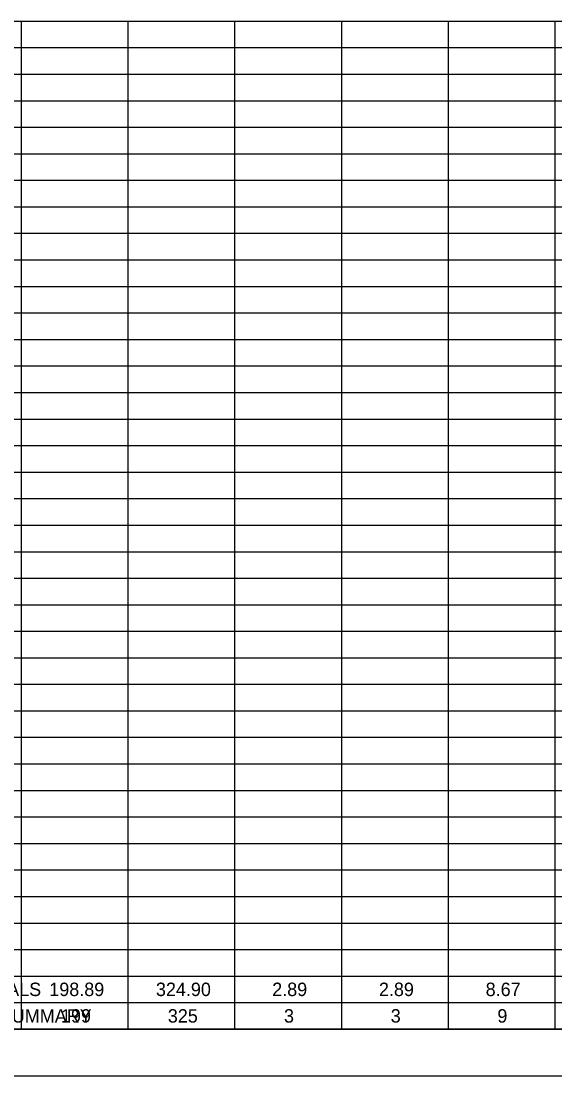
# Model space of a CAD drawing. Extents: x 0 to 34, y 0 to 22.
# Drawn here: x 10.32 to 16.02, y 0 to 11.28 of the extents above; entities that cross this region are included whole.
import ezdxf

# ---------------------------------------------------------------- set-up
doc = ezdxf.new("R2010")
doc.units = 0
for name, color, linetype in [('SH_Border', 7, 'Continuous'), ('SH_Cut_Line', 7, 'Continuous'), ('SH_Text', 7, 'Continuous')]:
    doc.layers.add(name, color=color, linetype=linetype)

msp = doc.modelspace()

# ---------------------------------------------------------------- linework, layer by layer
at = {"layer": 'SH_Border'}
msp.add_lwpolyline([(1.5, 21.5), (33.5, 21.5), (33.5, 0.5), (1.5, 0.5)], close=True, dxfattribs=at)
at = {"layer": 'SH_Cut_Line'}
msp.add_lwpolyline([(0, 0), (34, 0), (34, 22), (0, 22)], close=True, dxfattribs=at)
at = {"layer": 'SH_Text'}
for p, q in [((8.033, 11.284), (10.315, 11.284)), ((10.315, 11.284), (11.457, 11.284)), ((10.315, 11.284), (10.315, 10.149)), ((11.457, 11.284), (13.739, 11.284)), ((11.457, 11.284), (11.457, 10.149)), ((12.598, 11.284), (12.598, 10.149)), ((13.739, 11.284), (14.881, 11.284)), ((13.739, 11.284), (13.739, 10.149)), ((14.881, 11.284), (16.022, 11.284)), ((14.881, 11.284), (14.881, 10.149)), ((16.022, 11.284), (24.011, 11.284)), ((16.022, 11.284), (16.022, 10.149)), ((8.033, 11), (10.315, 11)), ((10.315, 11), (11.457, 11)), ((11.457, 11), (13.739, 11)), ((13.739, 11), (14.881, 11)), ((14.881, 11), (16.022, 11)), ((16.022, 11), (24.011, 11)), ((8.033, 10.716), (10.315, 10.716)), ((10.315, 10.716), (11.457, 10.716)), ((11.457, 10.716), (13.739, 10.716)), ((13.739, 10.716), (14.881, 10.716)), ((14.881, 10.716), (16.022, 10.716)), ((16.022, 10.716), (24.011, 10.716)), ((8.033, 10.432), (10.315, 10.432)), ((10.315, 10.432), (11.457, 10.432)), ((11.457, 10.432), (13.739, 10.432)), ((13.739, 10.432), (14.881, 10.432)), ((14.881, 10.432), (16.022, 10.432)), ((16.022, 10.432), (24.011, 10.432)), ((8.033, 10.149), (10.315, 10.149)), ((10.315, 10.149), (11.457, 10.149)), ((10.315, 10.149), (10.315, 9.581)), ((11.457, 10.149), (13.739, 10.149)), ((11.457, 10.149), (11.457, 9.581)), ((12.598, 10.149), (12.598, 9.581)), ((13.739, 10.149), (14.881, 10.149)), ((13.739, 10.149), (13.739, 9.581)), ((14.881, 10.149), (16.022, 10.149)), ((14.881, 10.149), (14.881, 9.581)), ((16.022, 10.149), (24.011, 10.149)), ((16.022, 10.149), (16.022, 9.581)), ((8.033, 9.865), (10.315, 9.865)), ((10.315, 9.865), (11.457, 9.865)), ((11.457, 9.865), (13.739, 9.865)), ((13.739, 9.865), (14.881, 9.865)), ((14.881, 9.865), (16.022, 9.865)), ((16.022, 9.865), (24.011, 9.865)), ((8.033, 9.581), (10.315, 9.581)), ((10.315, 9.581), (11.457, 9.581)), ((10.315, 9.581), (10.315, 9.297)), ((11.457, 9.581), (13.739, 9.581)), ((11.457, 9.581), (11.457, 9.297)), ((12.598, 9.581), (12.598, 9.297)), ((13.739, 9.581), (14.881, 9.581)), ((13.739, 9.581), (13.739, 9.297)), ((14.881, 9.581), (16.022, 9.581)), ((14.881, 9.581), (14.881, 9.297)), ((16.022, 9.581), (24.011, 9.581)), ((16.022, 9.581), (16.022, 9.297)), ((8.033, 9.297), (10.315, 9.297)), ((10.315, 9.297), (11.457, 9.297)), ((10.315, 9.297), (10.315, 9.014)), ((11.457, 9.297), (13.739, 9.297)), ((11.457, 9.297), (11.457, 9.014)), ((12.598, 9.297), (12.598, 9.014)), ((13.739, 9.297), (14.881, 9.297)), ((13.739, 9.297), (13.739, 9.014)), ((14.881, 9.297), (16.022, 9.297)), ((14.881, 9.297), (14.881, 9.014)), ((16.022, 9.297), (24.011, 9.297)), ((16.022, 9.297), (16.022, 9.014)), ((8.033, 9.014), (10.315, 9.014)), ((10.315, 9.014), (11.457, 9.014)), ((10.315, 9.014), (10.315, 8.73)), ((11.457, 9.014), (13.739, 9.014)), ((11.457, 9.014), (11.457, 8.73)), ((12.598, 9.014), (12.598, 8.73)), ((13.739, 9.014), (14.881, 9.014)), ((13.739, 9.014), (13.739, 8.73)), ((14.881, 9.014), (16.022, 9.014)), ((14.881, 9.014), (14.881, 8.73)), ((16.022, 9.014), (24.011, 9.014)), ((16.022, 9.014), (16.022, 8.73)), ((8.033, 8.73), (10.315, 8.73)), ((10.315, 8.73), (11.457, 8.73)), ((10.315, 8.73), (10.315, 8.446)), ((11.457, 8.73), (13.739, 8.73)), ((11.457, 8.73), (11.457, 8.446)), ((12.598, 8.73), (12.598, 8.446)), ((13.739, 8.73), (14.881, 8.73)), ((13.739, 8.73), (13.739, 8.446)), ((14.881, 8.73), (16.022, 8.73)), ((14.881, 8.73), (14.881, 8.446)), ((16.022, 8.73), (24.011, 8.73)), ((16.022, 8.73), (16.022, 8.446)), ((8.033, 8.446), (10.315, 8.446)), ((10.315, 8.446), (11.457, 8.446)), ((10.315, 8.446), (10.315, 8.162)), ((11.457, 8.446), (13.739, 8.446)), ((11.457, 8.446), (11.457, 8.162)), ((12.598, 8.446), (12.598, 8.162)), ((13.739, 8.446), (14.881, 8.446)), ((13.739, 8.446), (13.739, 8.162)), ((14.881, 8.446), (16.022, 8.446)), ((14.881, 8.446), (14.881, 8.162)), ((16.022, 8.446), (24.011, 8.446)), ((16.022, 8.446), (16.022, 8.162)), ((8.033, 8.162), (10.315, 8.162)), ((10.315, 8.162), (11.457, 8.162)), ((10.315, 8.162), (10.315, 7.878)), ((11.457, 8.162), (13.739, 8.162)), ((11.457, 8.162), (11.457, 7.878)), ((12.598, 8.162), (12.598, 7.878)), ((13.739, 8.162), (14.881, 8.162)), ((13.739, 8.162), (13.739, 7.878)), ((14.881, 8.162), (16.022, 8.162)), ((14.881, 8.162), (14.881, 7.878)), ((16.022, 8.162), (24.011, 8.162)), ((16.022, 8.162), (16.022, 7.878)), ((8.033, 7.878), (10.315, 7.878)), ((10.315, 7.878), (11.457, 7.878)), ((10.315, 7.878), (10.315, 7.595)), ((11.457, 7.878), (13.739, 7.878)), ((11.457, 7.878), (11.457, 7.595)), ((12.598, 7.878), (12.598, 7.595)), ((13.739, 7.878), (14.881, 7.878)), ((13.739, 7.878), (13.739, 7.595)), ((14.881, 7.878), (16.022, 7.878)), ((14.881, 7.878), (14.881, 7.595)), ((16.022, 7.878), (24.011, 7.878)), ((16.022, 7.878), (16.022, 7.595)), ((8.033, 7.595), (10.315, 7.595)), ((10.315, 7.595), (11.457, 7.595)), ((10.315, 7.595), (10.315, 7.311)), ((11.457, 7.595), (13.739, 7.595)), ((11.457, 7.595), (11.457, 7.311)), ((12.598, 7.595), (12.598, 7.311)), ((13.739, 7.595), (14.881, 7.595)), ((13.739, 7.595), (13.739, 7.311)), ((14.881, 7.595), (16.022, 7.595)), ((14.881, 7.595), (14.881, 7.311)), ((16.022, 7.595), (24.011, 7.595)), ((16.022, 7.595), (16.022, 7.311)), ((8.033, 7.311), (10.315, 7.311)), ((10.315, 7.311), (11.457, 7.311)), ((10.315, 7.311), (10.315, 7.027)), ((11.457, 7.311), (13.739, 7.311)), ((11.457, 7.311), (11.457, 7.027)), ((12.598, 7.311), (12.598, 7.027)), ((13.739, 7.311), (14.881, 7.311)), ((13.739, 7.311), (13.739, 7.027)), ((14.881, 7.311), (16.022, 7.311)), ((14.881, 7.311), (14.881, 7.027)), ((16.022, 7.311), (24.011, 7.311)), ((16.022, 7.311), (16.022, 7.027)), ((8.033, 7.027), (10.315, 7.027)), ((10.315, 7.027), (11.457, 7.027)), ((10.315, 7.027), (10.315, 6.743)), ((11.457, 7.027), (13.739, 7.027)), ((11.457, 7.027), (11.457, 6.743)), ((12.598, 7.027), (12.598, 6.743)), ((13.739, 7.027), (14.881, 7.027)), ((13.739, 7.027), (13.739, 6.743)), ((14.881, 7.027), (16.022, 7.027)), ((14.881, 7.027), (14.881, 6.743)), ((16.022, 7.027), (24.011, 7.027)), ((16.022, 7.027), (16.022, 6.743)), ((8.033, 6.743), (10.315, 6.743)), ((10.315, 6.743), (11.457, 6.743)), ((10.315, 6.743), (10.315, 6.459)), ((11.457, 6.743), (13.739, 6.743)), ((11.457, 6.743), (11.457, 6.459)), ((12.598, 6.743), (12.598, 6.459)), ((13.739, 6.743), (14.881, 6.743)), ((13.739, 6.743), (13.739, 6.459)), ((14.881, 6.743), (16.022, 6.743)), ((14.881, 6.743), (14.881, 6.459)), ((16.022, 6.743), (24.011, 6.743)), ((16.022, 6.743), (16.022, 6.459)), ((8.033, 6.459), (10.315, 6.459)), ((10.315, 6.459), (11.457, 6.459)), ((10.315, 6.459), (10.315, 6.176)), ((11.457, 6.459), (13.739, 6.459)), ((11.457, 6.459), (11.457, 6.176)), ((12.598, 6.459), (12.598, 6.176)), ((13.739, 6.459), (14.881, 6.459)), ((13.739, 6.459), (13.739, 6.176)), ((14.881, 6.459), (16.022, 6.459)), ((14.881, 6.459), (14.881, 6.176)), ((16.022, 6.459), (24.011, 6.459)), ((16.022, 6.459), (16.022, 6.176)), ((8.033, 6.176), (10.315, 6.176)), ((10.315, 6.176), (11.457, 6.176)), ((10.315, 6.176), (10.315, 5.892)), ((11.457, 6.176), (13.739, 6.176)), ((11.457, 6.176), (11.457, 5.892)), ((12.598, 6.176), (12.598, 5.892)), ((13.739, 6.176), (14.881, 6.176)), ((13.739, 6.176), (13.739, 5.892)), ((14.881, 6.176), (16.022, 6.176)), ((14.881, 6.176), (14.881, 5.892)), ((16.022, 6.176), (24.011, 6.176)), ((16.022, 6.176), (16.022, 5.892)), ((8.033, 5.892), (10.315, 5.892)), ((10.315, 5.892), (11.457, 5.892)), ((10.315, 5.892), (10.315, 5.608)), ((11.457, 5.892), (13.739, 5.892)), ((11.457, 5.892), (11.457, 5.608)), ((12.598, 5.892), (12.598, 5.608)), ((13.739, 5.892), (14.881, 5.892)), ((13.739, 5.892), (13.739, 5.608)), ((14.881, 5.892), (16.022, 5.892)), ((14.881, 5.892), (14.881, 5.608)), ((16.022, 5.892), (24.011, 5.892)), ((16.022, 5.892), (16.022, 5.608)), ((8.033, 5.608), (10.315, 5.608)), ((10.315, 5.608), (11.457, 5.608)), ((10.315, 5.608), (10.315, 5.324)), ((11.457, 5.608), (13.739, 5.608)), ((11.457, 5.608), (11.457, 5.324)), ((12.598, 5.608), (12.598, 5.324)), ((13.739, 5.608), (14.881, 5.608)), ((13.739, 5.608), (13.739, 5.324)), ((14.881, 5.608), (16.022, 5.608)), ((14.881, 5.608), (14.881, 5.324)), ((16.022, 5.608), (24.011, 5.608)), ((16.022, 5.608), (16.022, 5.324)), ((8.033, 5.324), (10.315, 5.324)), ((10.315, 5.324), (11.457, 5.324)), ((10.315, 5.324), (10.315, 4.757)), ((11.457, 5.324), (13.739, 5.324)), ((11.457, 5.324), (11.457, 4.757)), ((12.598, 5.324), (12.598, 4.757)), ((13.739, 5.324), (14.881, 5.324)), ((13.739, 5.324), (13.739, 4.757)), ((14.881, 5.324), (16.022, 5.324)), ((14.881, 5.324), (14.881, 4.757)), ((16.022, 5.324), (24.011, 5.324)), ((16.022, 5.324), (16.022, 4.757)), ((8.033, 5.041), (10.315, 5.041)), ((10.315, 5.041), (11.457, 5.041)), ((11.457, 5.041), (13.739, 5.041)), ((13.739, 5.041), (14.881, 5.041)), ((14.881, 5.041), (16.022, 5.041)), ((16.022, 5.041), (24.011, 5.041)), ((8.033, 4.757), (10.315, 4.757)), ((10.315, 4.757), (11.457, 4.757)), ((10.315, 4.757), (10.315, 4.473)), ((11.457, 4.757), (13.739, 4.757)), ((11.457, 4.757), (11.457, 4.473)), ((12.598, 4.757), (12.598, 4.473)), ((13.739, 4.757), (14.881, 4.757)), ((13.739, 4.757), (13.739, 4.473)), ((14.881, 4.757), (16.022, 4.757)), ((14.881, 4.757), (14.881, 4.473)), ((16.022, 4.757), (24.011, 4.757)), ((16.022, 4.757), (16.022, 4.473)), ((8.033, 4.473), (10.315, 4.473)), ((10.315, 4.473), (11.457, 4.473)), ((10.315, 4.473), (10.315, 4.189)), ((11.457, 4.473), (13.739, 4.473)), ((11.457, 4.473), (11.457, 4.189)), ((12.598, 4.473), (12.598, 4.189)), ((13.739, 4.473), (14.881, 4.473)), ((13.739, 4.473), (13.739, 4.189)), ((14.881, 4.473), (16.022, 4.473)), ((14.881, 4.473), (14.881, 4.189)), ((16.022, 4.473), (24.011, 4.473)), ((16.022, 4.473), (16.022, 4.189)), ((8.033, 4.189), (10.315, 4.189)), ((10.315, 4.189), (11.457, 4.189)), ((10.315, 4.189), (10.315, 3.905)), ((11.457, 4.189), (13.739, 4.189)), ((11.457, 4.189), (11.457, 3.905)), ((12.598, 4.189), (12.598, 3.905)), ((13.739, 4.189), (14.881, 4.189)), ((13.739, 4.189), (13.739, 3.905)), ((14.881, 4.189), (16.022, 4.189)), ((14.881, 4.189), (14.881, 3.905)), ((16.022, 4.189), (24.011, 4.189)), ((16.022, 4.189), (16.022, 3.905)), ((8.033, 3.905), (10.315, 3.905)), ((10.315, 3.905), (11.457, 3.905)), ((10.315, 3.905), (10.315, 3.338)), ((11.457, 3.905), (13.739, 3.905)), ((11.457, 3.905), (11.457, 3.338)), ((12.598, 3.905), (12.598, 3.338)), ((13.739, 3.905), (14.881, 3.905)), ((13.739, 3.905), (13.739, 3.338)), ((14.881, 3.905), (16.022, 3.905)), ((14.881, 3.905), (14.881, 3.338)), ((16.022, 3.905), (24.011, 3.905)), ((16.022, 3.905), (16.022, 3.338)), ((8.033, 3.622), (10.315, 3.622)), ((10.315, 3.622), (11.457, 3.622)), ((11.457, 3.622), (13.739, 3.622)), ((13.739, 3.622), (14.881, 3.622)), ((14.881, 3.622), (16.022, 3.622)), ((16.022, 3.622), (24.011, 3.622)), ((8.033, 3.338), (10.315, 3.338)), ((10.315, 3.338), (11.457, 3.338)), ((10.315, 3.338), (10.315, 3.054)), ((11.457, 3.338), (13.739, 3.338)), ((11.457, 3.338), (11.457, 3.054)), ((12.598, 3.338), (12.598, 3.054)), ((13.739, 3.338), (14.881, 3.338)), ((13.739, 3.338), (13.739, 3.054)), ((14.881, 3.338), (16.022, 3.338)), ((14.881, 3.338), (14.881, 3.054)), ((16.022, 3.338), (24.011, 3.338)), ((16.022, 3.338), (16.022, 3.054)), ((8.033, 3.054), (10.315, 3.054)), ((10.315, 3.054), (11.457, 3.054)), ((10.315, 3.054), (10.315, 2.77)), ((11.457, 3.054), (13.739, 3.054)), ((11.457, 3.054), (11.457, 2.77)), ((12.598, 3.054), (12.598, 2.77)), ((13.739, 3.054), (14.881, 3.054)), ((13.739, 3.054), (13.739, 2.77)), ((14.881, 3.054), (16.022, 3.054)), ((14.881, 3.054), (14.881, 2.77)), ((16.022, 3.054), (24.011, 3.054)), ((16.022, 3.054), (16.022, 2.77)), ((8.033, 2.77), (10.315, 2.77)), ((10.315, 2.77), (11.457, 2.77)), ((10.315, 2.77), (10.315, 2.486)), ((11.457, 2.77), (13.739, 2.77)), ((11.457, 2.77), (11.457, 2.486)), ((12.598, 2.77), (12.598, 2.486)), ((13.739, 2.77), (14.881, 2.77)), ((13.739, 2.77), (13.739, 2.486)), ((14.881, 2.77), (16.022, 2.77)), ((14.881, 2.77), (14.881, 2.486)), ((16.022, 2.77), (24.011, 2.77)), ((16.022, 2.77), (16.022, 2.486)), ((8.033, 2.486), (10.315, 2.486)), ((10.315, 2.486), (11.457, 2.486)), ((10.315, 2.486), (10.315, 1.919)), ((11.457, 2.486), (13.739, 2.486)), ((11.457, 2.486), (11.457, 1.919)), ((12.598, 2.486), (12.598, 1.919)), ((13.739, 2.486), (14.881, 2.486)), ((13.739, 2.486), (13.739, 1.919)), ((14.881, 2.486), (16.022, 2.486)), ((14.881, 2.486), (14.881, 1.919)), ((16.022, 2.486), (24.011, 2.486)), ((16.022, 2.486), (16.022, 1.919)), ((8.033, 2.203), (10.315, 2.203)), ((10.315, 2.203), (11.457, 2.203)), ((11.457, 2.203), (13.739, 2.203)), ((13.739, 2.203), (14.881, 2.203)), ((14.881, 2.203), (16.022, 2.203)), ((16.022, 2.203), (24.011, 2.203)), ((8.033, 1.919), (10.315, 1.919)), ((10.315, 1.919), (11.457, 1.919)), ((10.315, 1.919), (10.315, 1.635)), ((11.457, 1.919), (13.739, 1.919)), ((11.457, 1.919), (11.457, 1.635)), ((12.598, 1.919), (12.598, 1.635)), ((13.739, 1.919), (14.881, 1.919)), ((13.739, 1.919), (13.739, 1.635)), ((14.881, 1.919), (16.022, 1.919)), ((14.881, 1.919), (14.881, 1.635)), ((16.022, 1.919), (24.011, 1.919)), ((16.022, 1.919), (16.022, 1.635)), ((8.033, 1.635), (10.315, 1.635)), ((10.315, 1.635), (11.457, 1.635)), ((10.315, 1.635), (10.315, 1.351)), ((11.457, 1.635), (13.739, 1.635)), ((11.457, 1.635), (11.457, 1.351)), ((12.598, 1.635), (12.598, 1.351)), ((13.739, 1.635), (14.881, 1.635)), ((13.739, 1.635), (13.739, 1.351)), ((14.881, 1.635), (16.022, 1.635)), ((14.881, 1.635), (14.881, 1.351)), ((16.022, 1.635), (24.011, 1.635)), ((16.022, 1.635), (16.022, 1.351)), ((8.033, 1.351), (10.315, 1.351)), ((10.315, 1.351), (11.457, 1.351)), ((10.315, 1.351), (10.315, 1.068)), ((11.457, 1.351), (13.739, 1.351)), ((11.457, 1.351), (11.457, 1.068)), ((12.598, 1.351), (12.598, 1.068)), ((13.739, 1.351), (14.881, 1.351)), ((13.739, 1.351), (13.739, 1.068)), ((14.881, 1.351), (16.022, 1.351)), ((14.881, 1.351), (14.881, 1.068)), ((16.022, 1.351), (24.011, 1.351)), ((16.022, 1.351), (16.022, 1.068)), ((8.033, 1.068), (10.315, 1.068)), ((10.315, 1.068), (11.457, 1.068)), ((10.315, 1.068), (10.315, 0.5)), ((11.457, 1.068), (13.739, 1.068)), ((11.457, 1.068), (11.457, 0.5)), ((12.598, 1.068), (12.598, 0.5)), ((13.739, 1.068), (14.881, 1.068)), ((13.739, 1.068), (13.739, 0.5)), ((14.881, 1.068), (16.022, 1.068)), ((14.881, 1.068), (14.881, 0.5)), ((16.022, 1.068), (24.011, 1.068)), ((16.022, 1.068), (16.022, 0.5)), ((8.033, 0.784), (10.315, 0.784)), ((10.315, 0.784), (11.457, 0.784)), ((11.457, 0.784), (13.739, 0.784)), ((13.739, 0.784), (14.881, 0.784)), ((14.881, 0.784), (16.022, 0.784)), ((16.022, 0.784), (24.011, 0.784)), ((8.033, 0.5), (10.315, 0.5)), ((10.315, 0.5), (11.457, 0.5)), ((11.457, 0.5), (13.739, 0.5)), ((13.739, 0.5), (14.881, 0.5)), ((14.881, 0.5), (16.022, 0.5)), ((16.022, 0.5), (24.011, 0.5))]:
    msp.add_line(p, q, dxfattribs=at)

# ---------------------------------------------------------------- texts
for s, height, p in [('SUBTOTALS', 0.1436, (9.388, 0.854)), ('198.89', 0.1436, (10.617, 0.854)), ('324.90', 0.1436, (11.757, 0.854)), ('2.89', 0.1436, (13, 0.854)), ('2.89', 0.1436, (14.141, 0.854)), ('8.67', 0.1436, (15.282, 0.854)), ('TOTALS CARRIED TO GENERAL SUMMARY', 0.14358, (7.08, 0.57)), ('199', 0.1436, (10.742, 0.57)), ('325', 0.1436, (11.884, 0.57)), ('3', 0.144, (13.126, 0.57)), ('3', 0.144, (14.267, 0.57)), ('9', 0.144, (15.407, 0.57))]:
    msp.add_text(s, height=height, dxfattribs=at).set_placement(p)

doc.saveas('drawing.dxf')
